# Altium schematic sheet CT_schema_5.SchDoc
size 430 x 429 mm
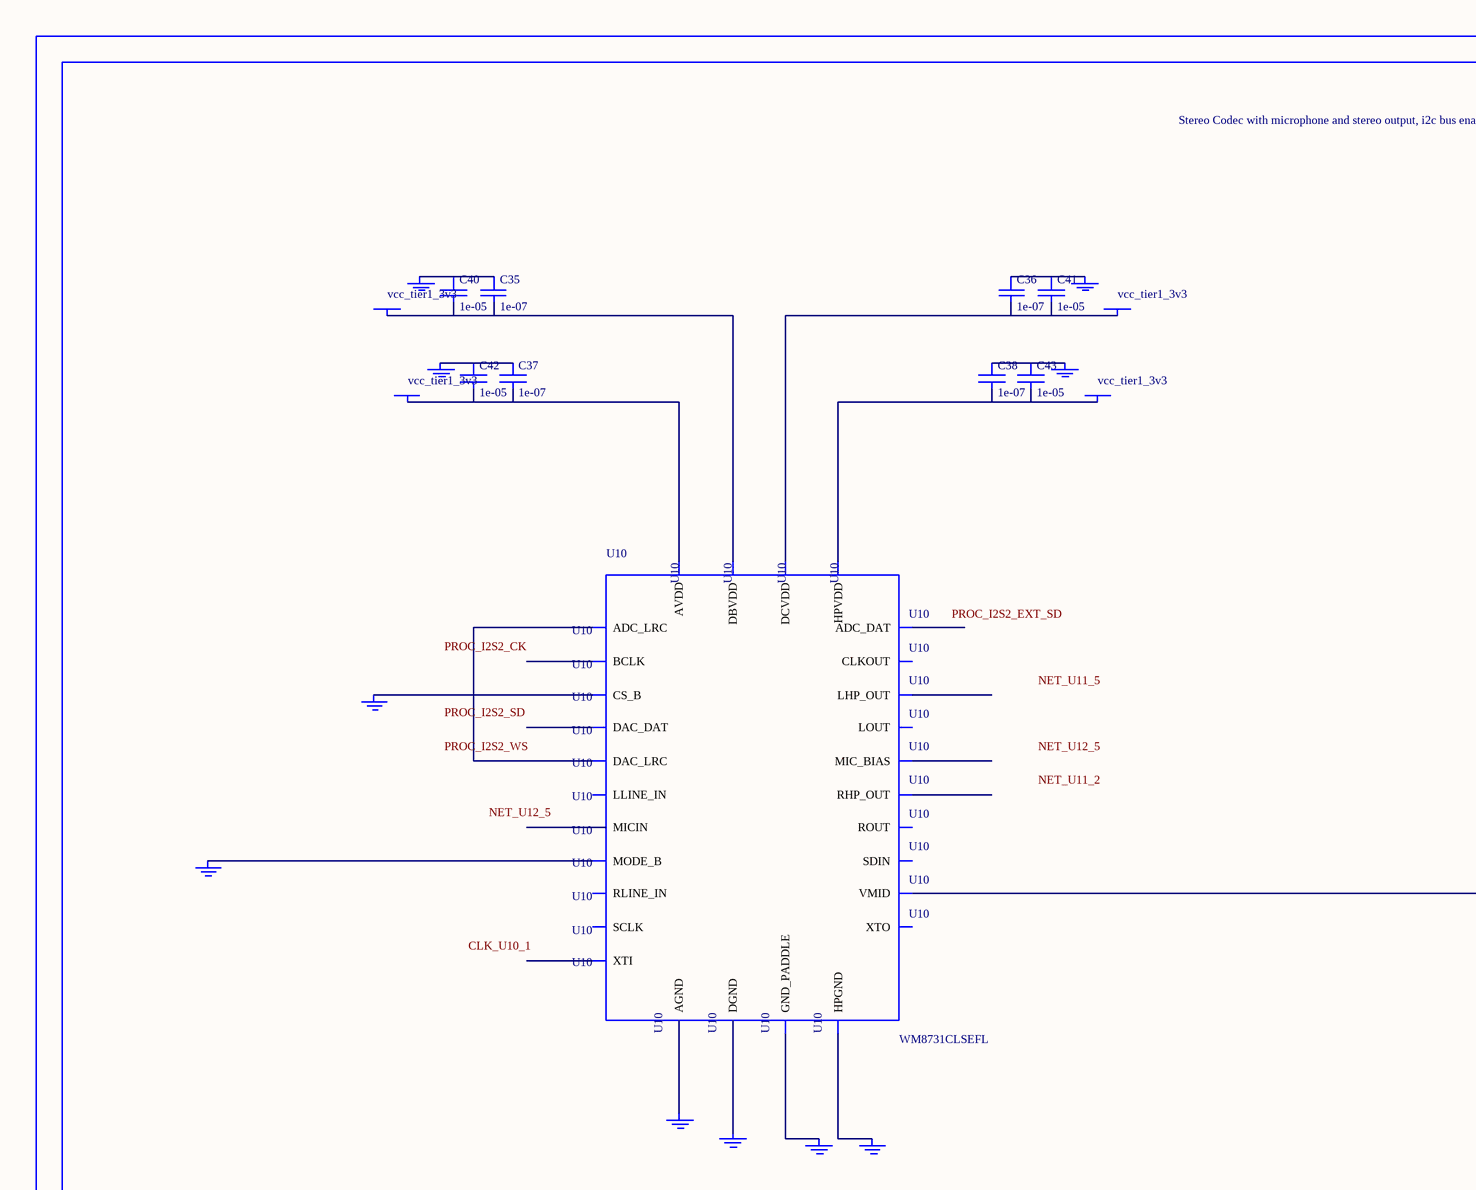
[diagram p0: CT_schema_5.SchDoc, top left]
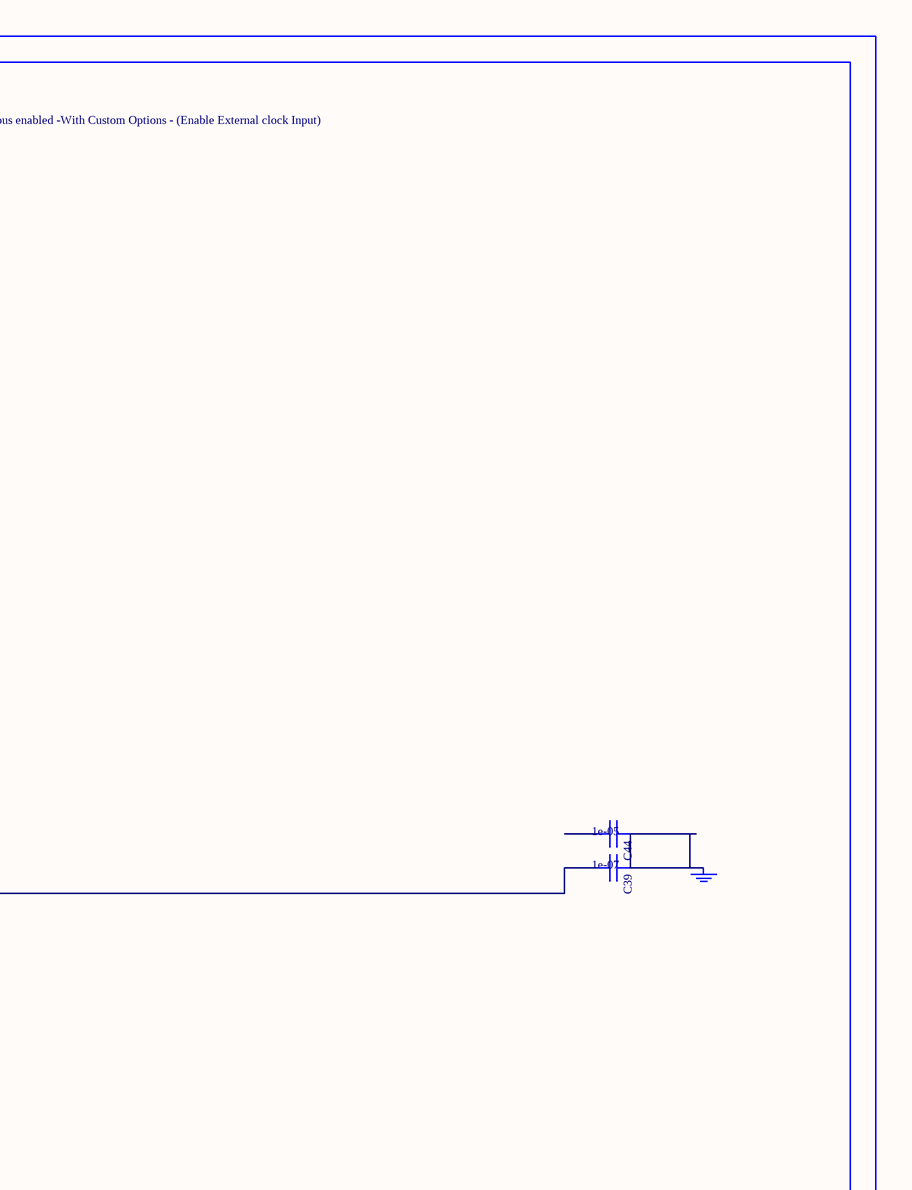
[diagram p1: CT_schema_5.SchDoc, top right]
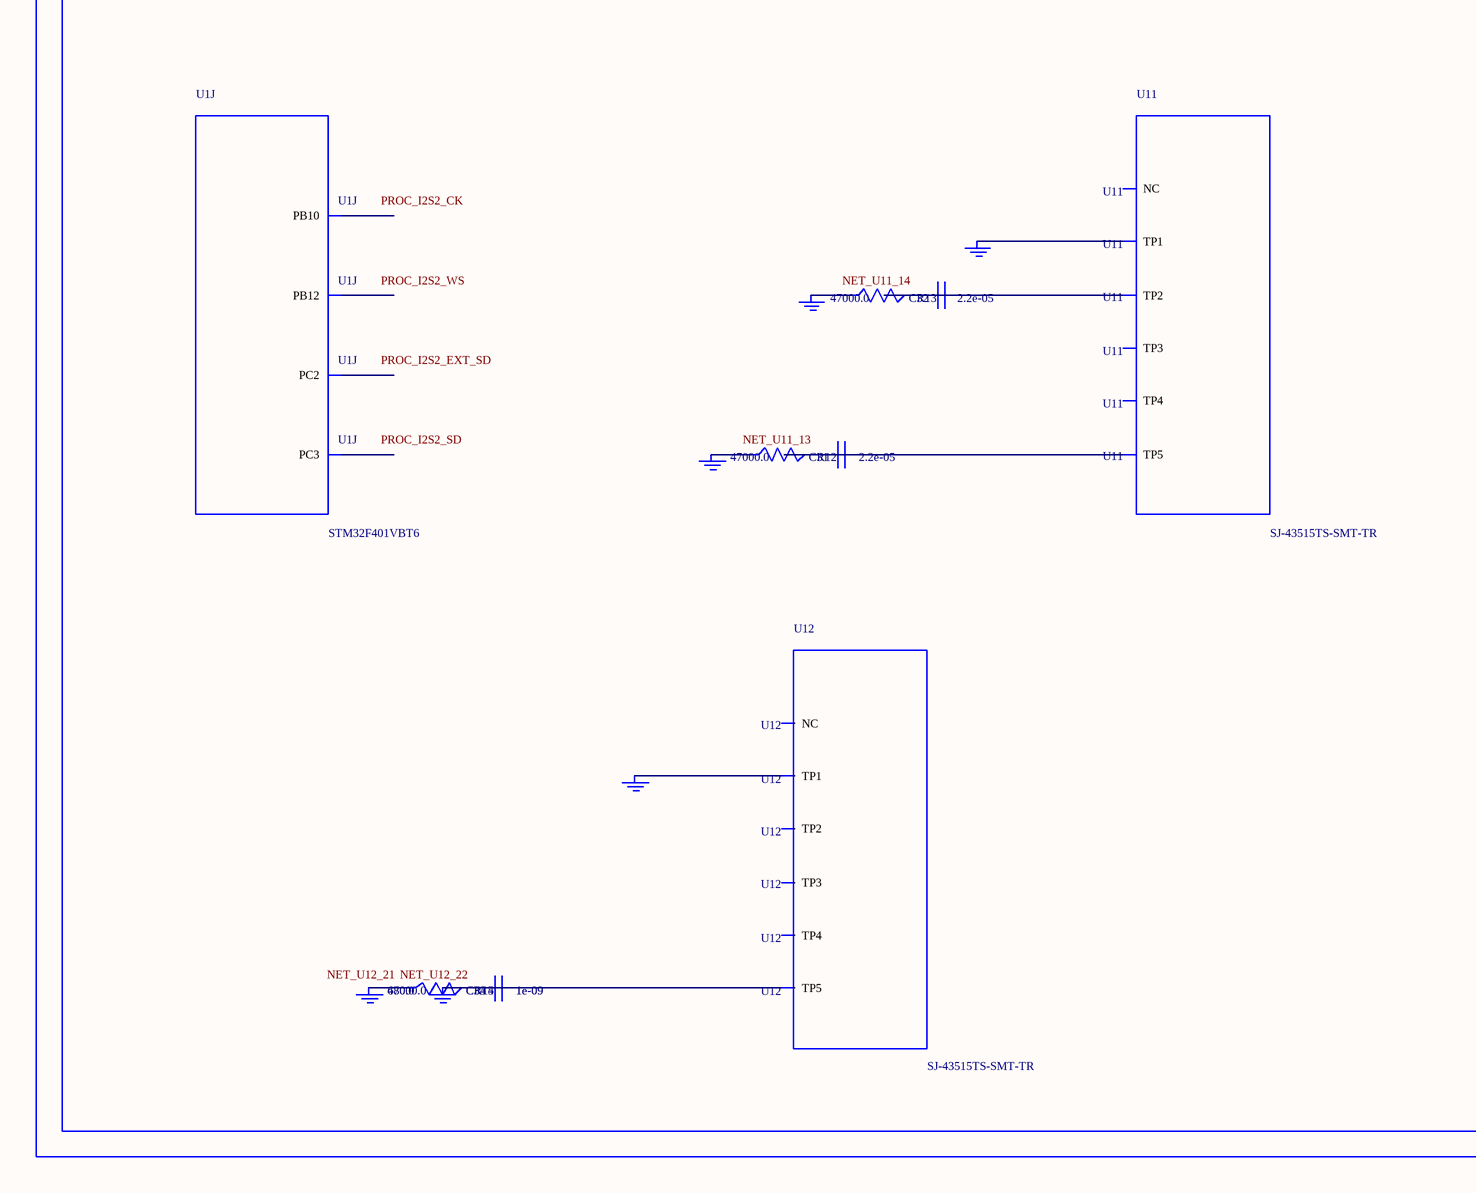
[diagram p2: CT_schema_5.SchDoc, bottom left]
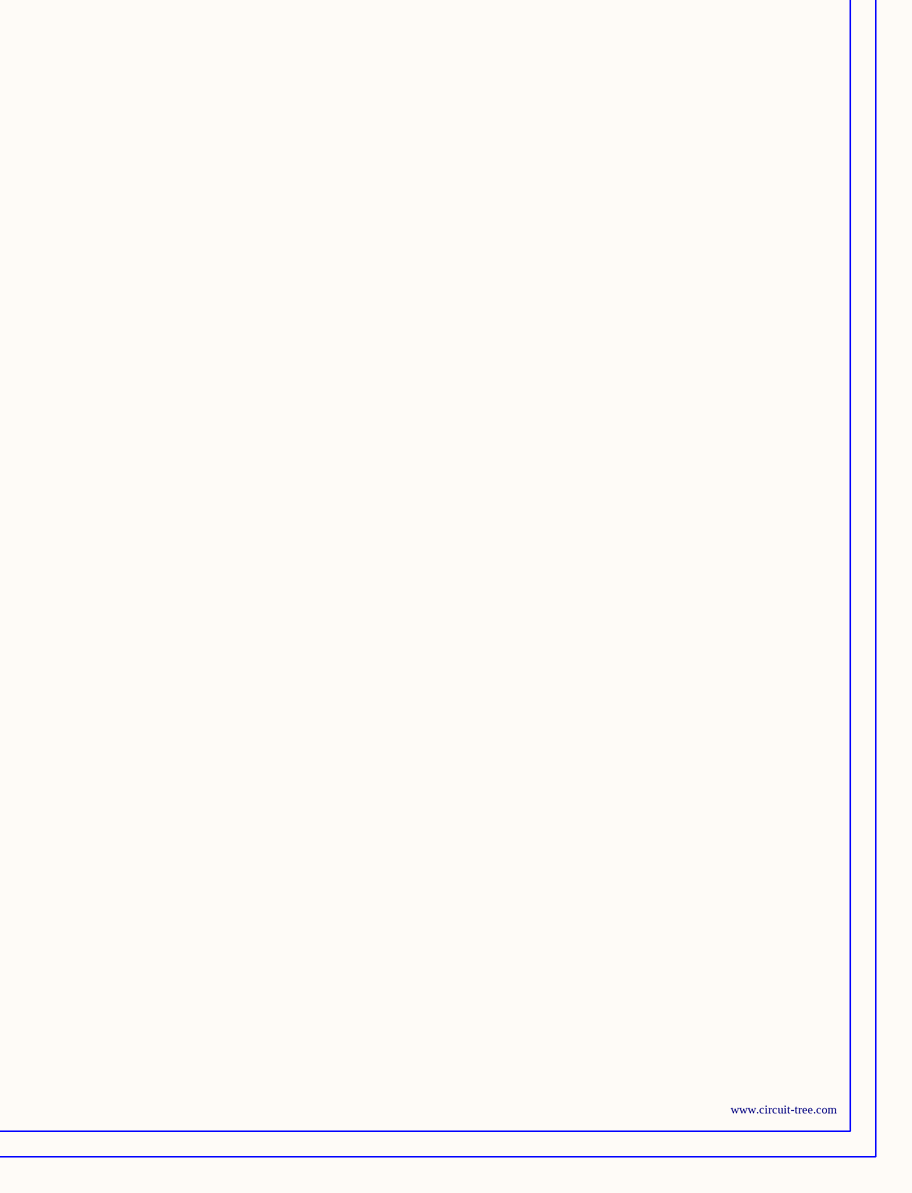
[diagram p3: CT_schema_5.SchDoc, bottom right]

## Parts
BORDER4  (no value)
C31  2.2e-05  [C1210]
C32  2.2e-05  [C1210]
C33  1e-09  [C0402]
C34  1e-09  [C0402]
C35  1e-07  [C0402]
C36  1e-07  [C0402]
C37  1e-07  [C0402]
C38  1e-07  [C0402]
C39  1e-07  [C0402]
C40  1e-05  [C0805]
C41  1e-05  [C0805]
C42  1e-05  [C0805]
C43  1e-05  [C0805]
C44  1e-05  [C0805]
GND_INSTANCE_4_0  (no value)
GND_INSTANCE_4_1  (no value)
GND_INSTANCE_4_2  (no value)
GND_INSTANCE_4_3  (no value)
GND_INSTANCE_4_4  (no value)
GND_INSTANCE_4_5  (no value)
GND_INSTANCE_4_6  (no value)
GND_INSTANCE_4_7  (no value)
GND_INSTANCE_4_8  (no value)
GND_INSTANCE_4_9  (no value)
GND_INSTANCE_4_10  (no value)
GND_INSTANCE_4_11  (no value)
GND_INSTANCE_4_12  (no value)
GND_INSTANCE_4_13  (no value)
GND_INSTANCE_4_14  (no value)
GND_INSTANCE_4_15  (no value)
GND_INSTANCE_4_16  (no value)
POWER_INSTANCE_4_0  vcc_tier1_3v3
POWER_INSTANCE_4_1  vcc_tier1_3v3
POWER_INSTANCE_4_2  vcc_tier1_3v3
POWER_INSTANCE_4_3  vcc_tier1_3v3
R12  47000.0  [R0603]
R13  47000.0  [R0603]
R14  47000.0  [R0603]
R15  680.0  [R0603]
U1  STM32F401VBT6  [LQFP100]  (part J of 10)
U10  WM8731CLSEFL  [QFN-28]
U11  SJ-43515TS-SMT-TR  [SJ-43515TS-SMT-TR]
U12  SJ-43515TS-SMT-TR  [SJ-43515TS-SMT-TR]

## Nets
NetC31_1: C31.1 C31.2 R12.2 U11.5(TP5)
NetC32_1: C32.1 C32.2 R13.2 U11.2(TP2)
NetC33_1: C33.1 C33.2 C34.1 C34.2 GND_INSTANCE_4_16.0(GND) R14.2 R15.2 U12.5(TP5)
NetC35_1: C35.1 C40.1 GND_INSTANCE_4_1.0(GND)
NetC35_2: C35.2 C40.2 POWER_INSTANCE_4_1.0(PWR) U10.5(DBVDD)
NetC36_1: C36.1 C41.1 GND_INSTANCE_4_0.0(GND)
NetC36_2: C36.2 C41.2 POWER_INSTANCE_4_0.0(PWR) U10.3(DCVDD)
NetC37_1: C37.1 C42.1 GND_INSTANCE_4_4.0(GND)
NetC37_2: C37.2 C42.2 POWER_INSTANCE_4_3.0(PWR) U10.18(AVDD)
NetC38_1: C38.1 C43.1 GND_INSTANCE_4_2.0(GND)
NetC38_2: C38.2 C43.2 POWER_INSTANCE_4_2.0(PWR) U10.12(HPVDD)
NetC39_1: C39.1 C44.1 GND_INSTANCE_4_5.0(GND)
NetC39_2: C39.2 U10.20(VMID)
NetGND_INSTANCE_4_3_0: GND_INSTANCE_4_3.0(GND) U10.15(HPGND)
NetGND_INSTANCE_4_6_0: GND_INSTANCE_4_6.0(GND) U10.25(MODE_B)
NetGND_INSTANCE_4_7_0: GND_INSTANCE_4_7.0(GND) U10.26(CS_B)
NetGND_INSTANCE_4_8_0: GND_INSTANCE_4_8.0(GND) U10.29(GND_PADDLE)
NetGND_INSTANCE_4_9_0: GND_INSTANCE_4_9.0(GND) U10.4(DGND)
NetGND_INSTANCE_4_10_0: GND_INSTANCE_4_10.0(GND) U10.19(AGND)
NetGND_INSTANCE_4_11_0: GND_INSTANCE_4_11.0(GND) U11.1(TP1)
NetGND_INSTANCE_4_12_0: GND_INSTANCE_4_12.0(GND) R13.1
NetGND_INSTANCE_4_13_0: GND_INSTANCE_4_13.0(GND) R12.1
NetGND_INSTANCE_4_14_0: GND_INSTANCE_4_14.0(GND) U12.1(TP1)
NetGND_INSTANCE_4_15_0: GND_INSTANCE_4_15.0(GND) R14.1 R15.1
NetU10_9: U10.9(DAC_LRC) U10.11(ADC_LRC)

Not connected (* = marked no-connect by the designer): C44 2; U1 17(PC2) 18(PC3) 47(PB10) 51(PB12); U10 1(XTI) 2(XTO) 6(CLKOUT) 7(BCLK) 8(DAC_DAT) 10(ADC_DAT) 13(LHP_OUT) 14(RHP_OUT) 16(LOUT) 17(ROUT) 21(MIC_BIAS) 22(MICIN) 23(RLINE_IN) 24(LLINE_IN) 27(SDIN) 28(SCLK); U11 3(TP3) 4(TP4) 6(NC); U12 2(TP2) 3(TP3) 4(TP4) 6(NC)

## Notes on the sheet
- Labels drawn without touching a wire or pin: CLK_U10_1, NET_U11_2, NET_U11_5, NET_U11_13, NET_U11_14, NET_U12_5, NET_U12_21, NET_U12_22, PROC_I2S2_CK, PROC_I2S2_EXT_SD, PROC_I2S2_SD, PROC_I2S2_WS

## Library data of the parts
BORDER4 = BORDER_PAGE4
C31 C32 = C1210C224K5RACTU
C33 C34 = C0402C102K3RAC
C35-C39 = C0402C104K3RACTU
C40-C44 = C0805C106K8RACTU
GND_INSTANCE_4_0-GND_INSTANCE_4_16 = GND
POWER_INSTANCE_4_0-POWER_INSTANCE_4_3 = PWR
R12-R14 = RC0603JR-0747KL
R15 = RC0603JR-07680RL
